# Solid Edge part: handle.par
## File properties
Title: Handle
Author: Deepak Maini
Template: Normal.par
Last saved by: Robert a Rhodes jr
Revision: 4
Application: Solid Edge
Material: aluminum
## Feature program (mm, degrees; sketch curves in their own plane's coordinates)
sketch for "unnamed RevolvedProtrusion 1" plane through (0, 0, 0) normal (0, -1, 0) x-axis (1, 0, 0)
  line (-87.868, 0.2971) -> (-87.868, -4)
  line (-87.868, -4) -> (-79.868, -4)
  line (-79.868, -4) -> (-79.868, -5)
  line (-79.868, -5) -> (76.132, -5)
  line (76.132, -5) -> (76.132, -4)
  line (76.132, -4) -> (84.132, -4)
  line (84.132, -4) -> (84.132, 0.2971)
revolve "unnamed RevolvedProtrusion 1" add finite 360 deg about sketch line (-87.868, 0.2971) -> (84.132, 0.2971)
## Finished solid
Body 1: solid body, 7 faces, 6 edges, 0 vertices.
  Faces by surface: plane 4, cylinder 3
  Edges by curve: circle 6
Bounding box of the edges (mm): 172.000 x 10.594 x 10.594, from (-87.868, -5.2971, -5) to (84.132, 5.2971, 5.5941).
Cylindrical faces by radius (mm): R4.2971 x2, R5.2971 x1
Planar faces by outward normal: +x 2, -x 2
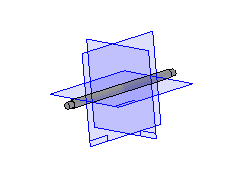
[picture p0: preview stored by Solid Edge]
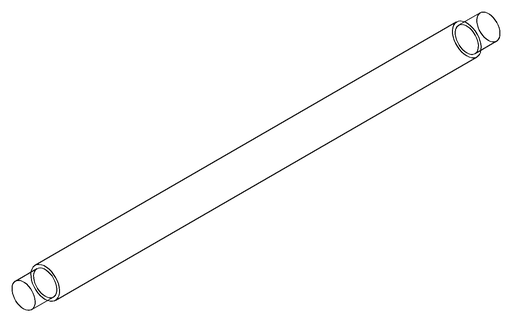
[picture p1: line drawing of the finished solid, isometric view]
